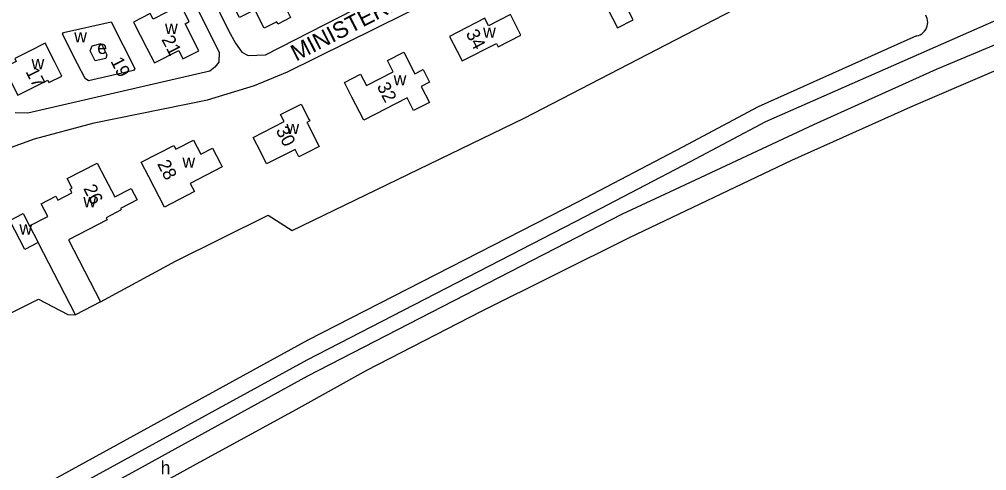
# Model space of a CAD drawing. Extents: x 162427 to 165104, y 384242 to 386287.
# Drawn here: x 163912.8 to 164205.6, y 384850.5 to 384987.1 of the extents above; entities that cross this region are included whole.
import ezdxf

# ---------------------------------------------------------------- set-up
doc = ezdxf.new("R2010")
doc.units = 0
for name, color, linetype in [('BLT_Basislijn', 7, 'Continuous'), ('BLT_Bebouwing', 7, 'Continuous'), ('BLT_Centroide', 7, 'Continuous'), ('BLT_Huisnummer', 7, 'Continuous'), ('BLT_Onderverdeling_panden', 7, 'Continuous'), ('BLT_Straatnaam', 7, 'Continuous')]:
    doc.layers.add(name, color=color, linetype=linetype)

msp = doc.modelspace()

# ---------------------------------------------------------------- linework, layer by layer
at = {"layer": 'BLT_Basislijn'}
for p, q in [((163962.18, 384999.38), (163973.24, 384977.11)), ((163973.24, 384977.11), (163973.14, 384974.15)), ((163970.44, 384971.44), (163915.3, 384958.72)), ((163971.99, 384972.71), (163970.44, 384971.44)), ((163973.14, 384974.15), (163971.99, 384972.71)), ((163915.3, 384958.72), (163911.48, 384958.83)), ((164081.9, 384931.88), (164000.1, 384889.99)), ((164084.22, 384927.45), (163999.78, 384883.99)), ((164095.31, 384928.13), (164000, 384879.09)), ((164000.1, 384889.99), (163919.34, 384845.68)), ((163999.78, 384883.99), (163921.76, 384841.31))]:
    msp.add_line(p, q, dxfattribs=at)
for points in [[(163874.37, 384930.96), (163895.29, 384941.69), (163907.09, 384947.2), (163917.37, 384950.98), (163935.42, 384955.81), (163969.74, 384962.82), (163983.96, 384967.15), (163993.92, 384971.28), (164109.67, 385028.61), (164113.77, 385032.85), (164114.66, 385034.28), (164116.64, 385039.21), (164117.08, 385045.22), (164111.4, 385081.45), (164102.85, 385139.32)], [(163940.13, 385055.09), (163960.26, 385016.14), (163976.07, 384983.78), (163978.19, 384979.93), (163980.14, 384977.23), (163981.99, 384976.21)], [(163981.99, 384976.21), (163987.3, 384976.37), (164032.07, 384999.44), (164033.82, 385001.29), (164034.1, 385002.11), (164034.23, 385004.85)], [(163937.33, 384901.61), (163960, 384913.99), (163988.04, 384927.89), (163995.38, 384923.27), (164065.59, 384957.24), (164134.64, 384992.97), (164140.11, 385003.48)], [(164223.8, 384993.71), (164138.65, 384956.12), (164115.85, 384944), (164084.22, 384927.45)], [(164226.47, 384987.1), (164190.35, 384971.95), (164153.21, 384955.24), (164109.58, 384934.79), (164095.31, 384928.13)], [(164184.41, 384982.15), (164184.97, 384982.29), (164185.5, 384982.51), (164185.99, 384982.8), (164186.44, 384983.16), (164186.84, 384983.58), (164187.17, 384984.05), (164187.44, 384984.55), (164187.63, 384985.1), (164187.75, 384985.66), (164187.78, 384986.23), (164187.74, 384986.8), (164187.62, 384987.37), (164187.42, 384987.91), (164187.17, 384988.37)], [(164184.41, 384982.15), (164136.46, 384960.62), (164113.52, 384948.42), (164081.9, 384931.88)], [(164229.12, 384980.5), (164183.46, 384960.96), (164146.56, 384944.41)], [(163934.78, 384979.13), (163937.53, 384979.8), (163939.29, 384976.44), (163938.9, 384975.31), (163935.76, 384974.61), (163934.21, 384977.64), (163934.78, 384979.13)], [(164146.56, 384944.41), (164097.39, 384921.01), (164052.57, 384898.66)], [(163894.44, 384890.39), (163918.51, 384902.42), (163927.41, 384897.84), (163929.71, 384897.69)], [(164052.57, 384898.66), (164017.86, 384880.8), (163997.33, 384869.41), (163965.35, 384851.94), (163909.44, 384821.18)], [(164000, 384879.09), (163946.83, 384849.82), (163921.52, 384836.03)]]:
    msp.add_lwpolyline(points, dxfattribs=at)
at = {"layer": 'BLT_Bebouwing'}
for p, q in [((163929.71, 384897.69), (163918.46, 384919.57)), ((163937.33, 384901.61), (163929.71, 384897.69))]:
    msp.add_line(p, q, dxfattribs=at)
for points in [[(164095.76, 384992.48), (164088.37, 385007.19), (164083.71, 385004.82), (164085.68, 385000.94), (164083.86, 385000), (164079.58, 384997.77), (164079.36, 384998.19), (164075.6, 384996.27), (164077.87, 384991.81), (164078.56, 384990.45), (164085.15, 384993.82), (164086.15, 384991.87), (164089.34, 384993.5), (164093.88, 384984.6), (164098.56, 384986.99), (164095.76, 384992.48)], [(163988.62, 385000), (163992.61, 384992.13), (163994.89, 384987.68), (163991.04, 384985.71), (163990.68, 384986.42), (163986.9, 384984.49), (163984.06, 384990.03), (163979.44, 384987.66), (163975.57, 384995.22), (163987.85, 385001.51), (163988.62, 385000)], [(163967.14, 384977.65), (163962.93, 384985.83), (163964.21, 384986.48), (163961.65, 384991.46), (163957.2, 384989.18), (163953.28, 384987.17), (163952.4, 384988.88), (163947.36, 384986.29), (163951.4, 384978.41), (163953.69, 384973.96), (163961, 384977.71), (163962.3, 384975.17), (163967.14, 384977.65)], [(163940.54, 384986.42), (163947.69, 384972.29), (163947.36, 384971.63), (163933.7, 384968.57), (163932.66, 384969.23), (163930.38, 384973.68), (163925.86, 384982.69), (163926.15, 384983.19), (163940.54, 384986.42)], [(164063.69, 384984.13), (164061.42, 384988.58), (164054.85, 384985.23), (164053.68, 384987.51), (164043.03, 384981.93), (164045.3, 384977.48), (164046.79, 384974.57), (164057.18, 384979.87), (164057.71, 384978.83), (164064.6, 384982.34), (164063.69, 384984.13)], [(163923.35, 384974.42), (163920.56, 384979.95), (163915.81, 384977.56), (163911.34, 384975.31), (163911.8, 384974.4), (163908.09, 384972.54), (163912.31, 384964.15), (163921.34, 384968.69), (163921.69, 384967.99), (163925.6, 384969.95), (163923.35, 384974.42)], [(164032.5, 384970.61), (164035.05, 384971.92), (164036.96, 384968.16), (164034.42, 384966.86), (164036.89, 384962.01), (164032.08, 384959.55), (164030.14, 384963.36), (164017.02, 384956.61), (164013.45, 384963.6), (164011.18, 384968.05), (164016.09, 384970.56), (164017.84, 384967.13), (164025.94, 384971.26), (164024.2, 384974.67), (164029.14, 384977.19), (164032.5, 384970.61)], [(164000, 384957.74), (164000.35, 384957.06), (164000.68, 384956.4), (164000, 384956.05), (163999.81, 384955.95), (164000, 384955.58), (164003.54, 384948.63), (164000, 384946.83), (163997.39, 384945.5), (163996.23, 384947.77), (163987.62, 384943.38), (163985.82, 384946.93), (163983.55, 384951.39), (163992.97, 384956.18), (163991.86, 384958.35), (163998.07, 384961.52), (164000, 384957.74)], [(163973.51, 384943.68), (163974.15, 384942.46), (163964.5, 384937.46), (163965.75, 384935.04), (163956.67, 384930.33), (163951.95, 384939.44), (163949.65, 384943.88), (163959.5, 384948.99), (163960.11, 384947.81), (163965.49, 384950.6), (163967.71, 384946.31), (163971.21, 384948.12), (163973.51, 384943.68)], [(163915.86, 384924.63), (163921.34, 384927.45), (163919.37, 384931.29), (163923.83, 384933.58), (163924.42, 384932.44), (163928.67, 384934.63), (163928.11, 384935.72), (163928.73, 384936.03), (163927.23, 384938.95), (163936.36, 384943.63), (163938.64, 384939.19)], [(163938.64, 384939.19), (163941.62, 384933.39), (163946.65, 384935.97), (163948.43, 384932.5), (163943.4, 384929.92), (163943.63, 384929.46), (163939.04, 384927.1), (163939.36, 384926.46), (163927.65, 384920.44), (163937.33, 384901.61)], [(163918.46, 384919.57), (163914.37, 384917.47), (163909.85, 384926.28), (163913.94, 384928.38), (163915.86, 384924.63)]]:
    msp.add_lwpolyline(points, dxfattribs=at)
at = {"layer": 'BLT_Onderverdeling_panden'}
msp.add_line((163915.86, 384924.63), (163918.46, 384919.57), dxfattribs=at)

# ---------------------------------------------------------------- texts
at = {"layer": 'BLT_Centroide'}
for s, p in [('w', (163929.36, 384980.18)), ('w', (163956.86, 384982.72)), ('w', (164053.16, 384981.56)), ('e', (163936.35, 384976.67)), ('w', (163916.44, 384972.06)), ('w', (164026.08, 384967.16)), ('w', (163993.62, 384952.44)), ('w', (163962.12, 384942.25)), ('w', (163932.14, 384930.27)), ('w', (163912.78, 384922.01)), ('h', (163955.53, 384849.41))]:
    msp.add_text(s, height=4, dxfattribs=at).set_placement(p)
at = {"layer": 'BLT_Huisnummer'}
for s, rotation, p in [('34', 297.0315, (164047.84, 384982.89)), ('21', 297.1902, (163955.72, 384981.06)), ('19', 297.0467, (163940.25, 384974.53)), ('17', 296.7151, (163914.56, 384971.35)), ('32', 297.0336, (164020.91, 384966.9)), ('30', 297.0007, (163990.3, 384953.54)), ('28', 297.4191, (163954.39, 384943.39)), ('26', 297.1852, (163932.03, 384935.96))]:
    msp.add_text(s, height=4, rotation=rotation, dxfattribs=at).set_placement(p)
at = {"layer": 'BLT_Straatnaam'}
msp.add_text('MINISTERLAAN', height=5, rotation=27.1771, dxfattribs=at).set_placement((163996.57, 384974.36))

doc.saveas('drawing.dxf')
